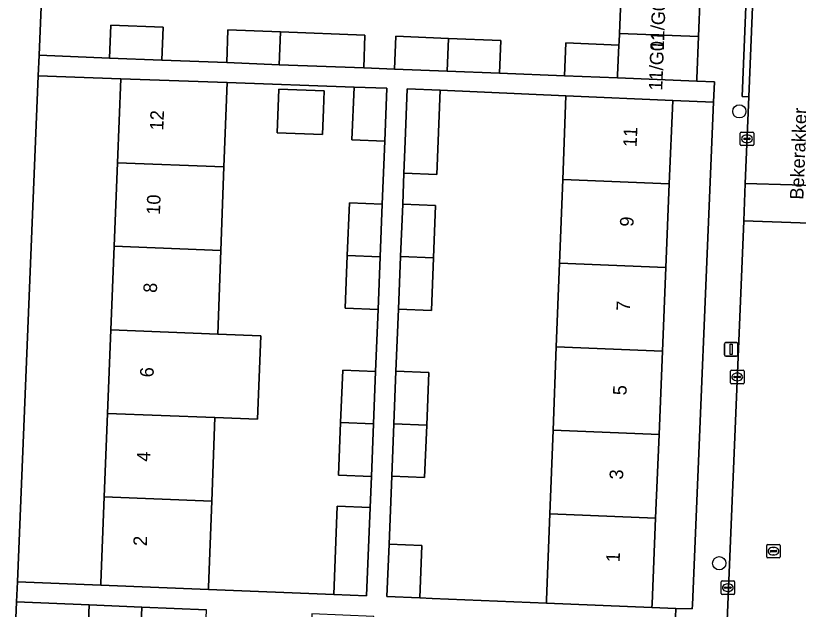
# Model space of a CAD drawing. Extents: x 161354 to 162026, y 386504 to 387460.
# Drawn here: x 161675.2 to 161732.9, y 386679.9 to 386723.6 of the extents above; entities that cross this region are included whole.
import ezdxf

# ---------------------------------------------------------------- set-up
doc = ezdxf.new("R2010")
doc.units = 0
for name, color, linetype in [('IMGEO_Boom', 7, 'Continuous'), ('IMGEO_Erf', 7, 'Continuous'), ('IMGEO_Kolk', 7, 'Continuous'), ('IMGEO_Lichtmast', 7, 'Continuous'), ('IMGEO_Openbare_ruimte_label', 7, 'Continuous'), ('IMGEO_Pand', 7, 'Continuous'), ('IMGEO_Pand_nummerreeks', 7, 'Continuous'), ('IMGEO_Rijbaan_lokaal_open', 7, 'Continuous'), ('IMGEO_Rioolput', 7, 'Continuous'), ('IMGEO_Voetpad_open', 7, 'Continuous')]:
    doc.layers.add(name, color=color, linetype=linetype)

msp = doc.modelspace()

# ---------------------------------------------------------------- linework, layer by layer
at = {"layer": 'IMGEO_Boom'}
for centre in [(161728.563, 386716.579), (161727.083, 386683.249)]:
    msp.add_circle(centre, 0.489, dxfattribs=at)
at = {"layer": 'IMGEO_Erf'}
for points in [[(161677.78, 386742.025), (161676.9, 386720.715), (161682.088, 386720.512), (161682.183, 386722.94), (161686.06, 386722.789), (161685.965, 386720.36), (161690.739, 386720.174), (161690.834, 386722.602), (161694.711, 386722.45), (161700.941, 386722.206), (161700.846, 386719.778), (161703.124, 386719.689), (161703.219, 386722.117), (161707.096, 386721.965), (161710.973, 386721.814), (161710.878, 386719.386), (161715.664, 386719.198), (161715.759, 386721.626), (161719.678, 386721.473), (161719.689, 386721.716), (161719.714, 386722.329), (161719.837, 386725.413)], [(161717.42, 386666.469), (161717.539, 386669.567), (161717.658, 386672.664), (161717.777, 386675.762), (161717.795, 386676.239), (161713.961, 386676.394), (161714.059, 386678.822), (161709.346, 386679.013), (161709.247, 386676.585), (161705.371, 386676.742), (161701.494, 386676.898), (161701.592, 386679.326), (161697.01, 386679.512), (161696.912, 386677.084), (161693.035, 386677.241), (161689.158, 386677.398), (161689.257, 386679.826), (161684.47, 386680.019), (161684.372, 386677.591), (161680.495, 386677.748), (161680.594, 386680.176), (161675.236, 386680.393), (161674.229, 386655.994)]]:
    msp.add_lwpolyline(points, dxfattribs=at)
for points in [[(161682.44, 386706.629), (161682.684, 386712.79), (161682.93, 386718.98), (161676.837, 386719.2), (161675.298, 386681.892), (161681.45, 386681.643), (161681.456, 386681.799), (161681.708, 386688.145), (161681.952, 386694.306), (161682.196, 386700.468)], [(161701.911, 386701.971), (161699.483, 386702.068), (161699.638, 386705.945), (161699.793, 386709.822), (161702.221, 386709.725), (161702.407, 386714.385), (161699.979, 386714.483), (161700.134, 386718.359), (161690.763, 386718.697), (161690.536, 386712.478), (161690.311, 386706.316), (161690.086, 386700.155), (161693.262, 386700.029), (161693.017, 386693.867), (161689.861, 386693.992), (161689.636, 386687.83), (161689.405, 386681.494), (161689.399, 386681.321), (161698.638, 386680.947), (161698.898, 386687.462), (161701.326, 386687.365), (161701.418, 386689.65), (161698.99, 386689.747), (161699.145, 386693.624), (161699.3, 386697.501), (161701.728, 386697.403)], [(161694.458, 386714.984), (161694.576, 386718.217), (161697.938, 386718.094), (161697.887, 386716.709), (161697.82, 386714.861)], [(161715.292, 386705.385), (161715.529, 386711.546), (161715.767, 386717.736), (161706.496, 386718.14), (161706.246, 386711.927), (161703.818, 386712.027), (161703.727, 386709.744), (161706.155, 386709.647), (161705.997, 386705.77), (161705.841, 386701.893), (161703.413, 386701.991), (161703.229, 386697.421), (161705.657, 386697.324), (161705.501, 386693.447), (161705.345, 386689.57), (161702.917, 386689.667), (161702.716, 386684.665), (161705.144, 386684.567), (161704.988, 386680.69), (161705.901, 386680.653), (161714.327, 386680.312), (161714.337, 386680.56), (161714.581, 386686.901), (161714.818, 386693.062), (161715.055, 386699.224)], [(161726.661, 386717.261), (161723.649, 386717.392), (161723.396, 386711.223), (161723.143, 386705.062), (161722.891, 386698.902), (161722.639, 386692.741), (161722.386, 386686.58), (161722.127, 386680.255), (161722.116, 386679.997), (161723.886, 386679.925), (161725.083, 386679.877), (161725.096, 386680.182)]]:
    msp.add_lwpolyline(points, close=True, dxfattribs=at)
at = {"layer": 'IMGEO_Kolk'}
for p, q in [((161728.625, 386714.128), (161728.625, 386714.98)), ((161728.7, 386715.054), (161729.552, 386715.054)), ((161729.113, 386714.834), (161729.138, 386714.834)), ((161729.626, 386714.98), (161729.626, 386714.128)), ((161728.884, 386714.548), (161728.884, 386714.56)), ((161729.322, 386714.511), (161728.924, 386714.511)), ((161728.927, 386714.597), (161729.325, 386714.597)), ((161729.136, 386714.274), (161729.111, 386714.274)), ((161729.368, 386714.56), (161729.368, 386714.548)), ((161729.552, 386714.054), (161728.7, 386714.054)), ((161727.983, 386697.49), (161728.835, 386697.49)), ((161727.908, 386696.564), (161727.908, 386697.416)), ((161728.167, 386696.984), (161728.167, 386696.996)), ((161728.605, 386696.947), (161728.207, 386696.947)), ((161728.21, 386697.033), (161728.608, 386697.033)), ((161728.396, 386697.27), (161728.421, 386697.27)), ((161728.651, 386696.996), (161728.651, 386696.984)), ((161728.909, 386697.416), (161728.909, 386696.564)), ((161728.835, 386696.49), (161727.983, 386696.49)), ((161728.419, 386696.71), (161728.394, 386696.71)), ((161727.215, 386681.024), (161727.215, 386681.876)), ((161727.29, 386681.95), (161728.142, 386681.95)), ((161728.216, 386681.876), (161728.216, 386681.024)), ((161727.474, 386681.444), (161727.474, 386681.456)), ((161727.912, 386681.407), (161727.514, 386681.407)), ((161727.517, 386681.493), (161727.915, 386681.493)), ((161727.703, 386681.73), (161727.728, 386681.73)), ((161727.958, 386681.456), (161727.958, 386681.444)), ((161728.142, 386680.95), (161727.29, 386680.95)), ((161727.726, 386681.17), (161727.701, 386681.17))]:
    msp.add_line(p, q, dxfattribs=at)
for points in [[(161728.625, 386714.128), (161728.625, 386714.98)], [(161728.7, 386715.054), (161729.552, 386715.054)], [(161729.626, 386714.98), (161729.626, 386714.128)], [(161729.552, 386714.054), (161728.7, 386714.054)], [(161727.983, 386697.49), (161728.835, 386697.49)], [(161727.908, 386696.564), (161727.908, 386697.416)], [(161728.909, 386697.416), (161728.909, 386696.564)], [(161728.835, 386696.49), (161727.983, 386696.49)], [(161727.215, 386681.024), (161727.215, 386681.876)], [(161727.29, 386681.95), (161728.142, 386681.95)], [(161728.216, 386681.876), (161728.216, 386681.024)], [(161728.142, 386680.95), (161727.29, 386680.95)]]:
    msp.add_lwpolyline(points, dxfattribs=at)
for centre, radius, start, end in [((161728.702, 386714.978), 0.0765, 91.55205, 178.44795), ((161728.702, 386714.978), 0.0765, 91.55205, 178.44795), ((161729.55, 386714.978), 0.0765, 1.55205, 88.44795), ((161729.55, 386714.978), 0.0765, 1.55205, 88.44795), ((161728.924, 386714.557), 0.0403, 85.87752, 175.75265), ((161728.921, 386714.547), 0.0366, 178.93798, 274.71019), ((161729.325, 386714.554), 0.043, 264.86636, 352.45326), ((161729.329, 386714.559), 0.0386, 1.73085, 96.63898), ((161728.702, 386714.13), 0.0765, 181.55205, 268.44795), ((161728.702, 386714.13), 0.0765, 181.55205, 268.44795), ((161729.55, 386714.13), 0.0765, 271.55205, 358.44795), ((161729.55, 386714.13), 0.0765, 271.55205, 358.44795), ((161727.985, 386697.414), 0.0765, 91.55205, 178.44795), ((161727.985, 386697.414), 0.0765, 91.55205, 178.44795), ((161728.833, 386697.414), 0.0765, 1.55205, 88.44795), ((161728.833, 386697.414), 0.0765, 1.55205, 88.44795), ((161728.207, 386696.993), 0.0403, 85.87752, 175.75265), ((161728.204, 386696.983), 0.0366, 178.93798, 274.71019), ((161728.608, 386696.99), 0.043, 264.86636, 352.45326), ((161728.612, 386696.995), 0.0386, 1.73085, 96.63898), ((161727.985, 386696.566), 0.0765, 181.55205, 268.44795), ((161727.985, 386696.566), 0.0765, 181.55205, 268.44795), ((161728.833, 386696.566), 0.0765, 271.55205, 358.44795), ((161728.833, 386696.566), 0.0765, 271.55205, 358.44795), ((161727.292, 386681.874), 0.0765, 91.55205, 178.44795), ((161727.292, 386681.874), 0.0765, 91.55205, 178.44795), ((161728.14, 386681.874), 0.0765, 1.55205, 88.44795), ((161728.14, 386681.874), 0.0765, 1.55205, 88.44795), ((161727.514, 386681.453), 0.0403, 85.87752, 175.75265), ((161727.511, 386681.443), 0.0366, 178.93798, 274.71019), ((161727.915, 386681.45), 0.043, 264.86636, 352.45326), ((161727.919, 386681.455), 0.0386, 1.73085, 96.63898), ((161727.292, 386681.026), 0.0765, 181.55205, 268.44795), ((161727.292, 386681.026), 0.0765, 181.55205, 268.44795), ((161728.14, 386681.026), 0.0765, 271.55205, 358.44795), ((161728.14, 386681.026), 0.0765, 271.55205, 358.44795)]:
    msp.add_arc(centre, radius, start, end, dxfattribs=at)
for centre, major_axis, ratio, start_param, end_param in [((161729.112, 386714.554), (-0.387, 0.002), 0.722429, 4.712389, 7.853982), ((161729.137, 386714.554), (-0.39, 0.002), 0.717154, 1.570796, 4.712389), ((161728.395, 386696.99), (-0.387, 0.002), 0.722429, 4.712389, 7.853982), ((161728.42, 386696.99), (-0.39, 0.002), 0.717154, 1.570796, 4.712389), ((161727.702, 386681.45), (-0.387, 0.002), 0.722429, 4.712389, 7.853982), ((161727.727, 386681.45), (-0.39, 0.002), 0.717154, 1.570796, 4.712389)]:
    msp.add_ellipse(centre, major_axis=major_axis, ratio=ratio, start_param=start_param, end_param=end_param, dxfattribs=at)
at = {"layer": 'IMGEO_Lichtmast'}
for p, q in [((161727.463, 386698.623), (161727.463, 386699.423)), ((161727.463, 386699.423), (161727.463, 386698.623)), ((161727.563, 386699.523), (161728.353, 386699.523)), ((161728.353, 386699.523), (161727.563, 386699.523)), ((161728.453, 386699.423), (161728.453, 386698.623)), ((161728.453, 386698.623), (161728.453, 386699.423)), ((161728.353, 386698.523), (161727.563, 386698.523)), ((161727.563, 386698.523), (161728.353, 386698.523))]:
    msp.add_line(p, q, dxfattribs=at)
msp.add_lwpolyline([(161727.883, 386699.398), (161728.033, 386699.398), (161728.033, 386698.648), (161727.883, 386698.648), (161727.883, 386699.398)], dxfattribs=at)
for centre, start, end in [((161727.563, 386699.423), 90, 180), ((161727.563, 386699.423), 90, 180), ((161728.353, 386699.423), 0, 90), ((161728.353, 386699.423), 360, 90), ((161727.563, 386698.623), 180, 270), ((161727.563, 386698.623), 180, 270), ((161728.353, 386698.623), 270, 0), ((161728.353, 386698.623), 270, 0)]:
    msp.add_arc(centre, 0.1, start, end, dxfattribs=at)
at = {"layer": 'IMGEO_Pand'}
for points in [[(161725.556, 386722.095), (161725.679, 386725.179), (161719.837, 386725.413), (161719.714, 386722.329)], [(161682.088, 386720.512), (161685.965, 386720.36), (161686.06, 386722.789), (161682.183, 386722.94)], [(161694.711, 386722.45), (161690.834, 386722.602), (161690.739, 386720.174), (161694.616, 386720.022)], [(161694.711, 386722.45), (161694.616, 386720.022), (161700.846, 386719.778), (161700.941, 386722.206)], [(161725.556, 386722.095), (161719.714, 386722.329), (161719.689, 386721.716), (161719.678, 386721.473), (161719.581, 386719.244), (161719.572, 386719.045), (161725.424, 386718.816), (161725.432, 386719.01)], [(161707.096, 386721.965), (161703.219, 386722.117), (161703.124, 386719.689), (161707.001, 386719.537)], [(161707.096, 386721.965), (161707.001, 386719.537), (161710.878, 386719.386), (161710.973, 386721.814)], [(161719.678, 386721.473), (161715.759, 386721.626), (161715.664, 386719.198), (161719.572, 386719.045), (161719.581, 386719.244)], [(161690.763, 386718.697), (161682.93, 386718.98), (161682.684, 386712.79), (161690.536, 386712.478)], [(161700.134, 386718.359), (161699.979, 386714.483), (161702.407, 386714.385), (161702.563, 386718.283)], [(161706.496, 386718.14), (161704.065, 386718.238), (161703.912, 386714.361), (161703.818, 386712.027), (161706.246, 386711.927)], [(161694.576, 386718.217), (161694.458, 386714.984), (161697.82, 386714.861), (161697.887, 386716.709), (161697.938, 386718.094)], [(161723.649, 386717.392), (161715.767, 386717.736), (161715.529, 386711.546), (161723.396, 386711.223)], [(161690.311, 386706.316), (161690.536, 386712.478), (161682.684, 386712.79), (161682.44, 386706.629)], [(161715.529, 386711.546), (161715.292, 386705.385), (161723.143, 386705.062), (161723.396, 386711.223)], [(161702.221, 386709.725), (161699.793, 386709.822), (161699.638, 386705.945), (161702.066, 386705.848)], [(161703.727, 386709.744), (161703.571, 386705.868), (161705.997, 386705.77), (161706.155, 386709.647)], [(161682.44, 386706.629), (161682.196, 386700.468), (161690.086, 386700.155), (161690.311, 386706.316)], [(161702.066, 386705.848), (161699.638, 386705.945), (161699.483, 386702.068), (161701.911, 386701.971)], [(161705.997, 386705.77), (161703.571, 386705.868), (161703.413, 386701.991), (161705.841, 386701.893)], [(161722.891, 386698.902), (161723.143, 386705.062), (161715.292, 386705.385), (161715.055, 386699.224)], [(161693.262, 386700.029), (161690.086, 386700.155), (161682.196, 386700.468), (161681.952, 386694.306), (161689.861, 386693.992), (161693.017, 386693.867)], [(161715.055, 386699.224), (161714.818, 386693.062), (161722.639, 386692.741), (161722.891, 386698.902)], [(161701.728, 386697.403), (161699.3, 386697.501), (161699.145, 386693.624), (161701.573, 386693.527)], [(161703.229, 386697.421), (161703.073, 386693.544), (161705.501, 386693.447), (161705.657, 386697.324)], [(161681.952, 386694.306), (161681.708, 386688.145), (161689.636, 386687.83), (161689.861, 386693.992)], [(161701.573, 386693.527), (161699.145, 386693.624), (161698.99, 386689.747), (161701.418, 386689.65)], [(161705.501, 386693.447), (161703.073, 386693.544), (161702.917, 386689.667), (161705.345, 386689.57)], [(161714.818, 386693.062), (161714.581, 386686.901), (161722.386, 386686.58), (161722.639, 386692.741)], [(161689.636, 386687.83), (161681.708, 386688.145), (161681.456, 386681.799), (161681.45, 386681.643), (161689.399, 386681.321), (161689.405, 386681.494)], [(161701.326, 386687.365), (161698.898, 386687.462), (161698.638, 386680.947), (161701.066, 386680.849)], [(161722.386, 386686.58), (161714.581, 386686.901), (161714.337, 386680.56), (161714.327, 386680.312), (161722.116, 386679.997), (161722.127, 386680.255)], [(161702.716, 386684.665), (161702.56, 386680.788), (161704.988, 386680.69), (161705.144, 386684.567)], [(161684.47, 386680.019), (161680.594, 386680.176), (161680.495, 386677.748), (161684.372, 386677.591)]]:
    msp.add_lwpolyline(points, close=True, dxfattribs=at)
at = {"layer": 'IMGEO_Rijbaan_lokaal_open'}
for points in [[(161737.515, 386750), (161737.664, 386757.8), (161738.131, 386768.811), (161731.175, 386769.153), (161730.711, 386758.025), (161730.697, 386753.106), (161730.304, 386743.254), (161730.096, 386738.148), (161729.261, 386717.657), (161729, 386711.269), (161735.937, 386711.052), (161736.362, 386721.528), (161736.628, 386728.094)], [(161735.824, 386708.256), (161735.937, 386711.052), (161729, 386711.269), (161728.888, 386708.517)]]:
    msp.add_lwpolyline(points, close=True, dxfattribs=at)
for points in [[(161674.229, 386655.994), (161675.236, 386680.393), (161675.298, 386681.892), (161676.837, 386719.2), (161676.9, 386720.715), (161677.78, 386742.025)], [(161735.471, 386699.54), (161735.824, 386708.256), (161728.888, 386708.517), (161728.502, 386699.051), (161727.654, 386679.034), (161726.868, 386660.492), (161726.622, 386654.699)]]:
    msp.add_lwpolyline(points, dxfattribs=at)
at = {"layer": 'IMGEO_Rioolput'}
for p, q in [((161730.579, 386683.716), (161730.579, 386684.568)), ((161730.654, 386684.642), (161731.506, 386684.642)), ((161730.881, 386684.185), (161731.279, 386684.185)), ((161731.067, 386684.422), (161731.092, 386684.422)), ((161731.58, 386684.568), (161731.58, 386683.716)), ((161731.506, 386683.642), (161730.654, 386683.642)), ((161730.838, 386684.136), (161730.838, 386684.148)), ((161731.276, 386684.099), (161730.878, 386684.099)), ((161731.09, 386683.862), (161731.065, 386683.862)), ((161731.322, 386684.148), (161731.322, 386684.136))]:
    msp.add_line(p, q, dxfattribs=at)
for points in [[(161730.579, 386683.716), (161730.579, 386684.568)], [(161730.654, 386684.642), (161731.506, 386684.642)], [(161731.58, 386684.568), (161731.58, 386683.716)], [(161731.506, 386683.642), (161730.654, 386683.642)]]:
    msp.add_lwpolyline(points, dxfattribs=at)
for centre, radius, start, end in [((161730.656, 386684.566), 0.0765, 91.55205, 178.44795), ((161730.656, 386684.566), 0.0765, 91.55205, 178.44795), ((161730.878, 386684.145), 0.0403, 85.87752, 175.75265), ((161731.283, 386684.147), 0.0386, 1.73085, 96.63898), ((161731.504, 386684.566), 0.0765, 1.55205, 88.44795), ((161731.504, 386684.566), 0.0765, 1.55205, 88.44795), ((161730.656, 386683.718), 0.0765, 181.55205, 268.44795), ((161730.656, 386683.718), 0.0765, 181.55205, 268.44795), ((161730.875, 386684.135), 0.0366, 178.93798, 274.71019), ((161731.279, 386684.142), 0.043, 264.86636, 352.45326), ((161731.504, 386683.718), 0.0765, 271.55205, 358.44795), ((161731.504, 386683.718), 0.0765, 271.55205, 358.44795)]:
    msp.add_arc(centre, radius, start, end, dxfattribs=at)
for centre, major_axis, ratio, start_param, end_param in [((161731.066, 386684.142), (-0.387, 0.002), 0.722429, 4.712389, 7.853982), ((161731.091, 386684.142), (-0.39, 0.002), 0.717154, 1.570796, 4.712389)]:
    msp.add_ellipse(centre, major_axis=major_axis, ratio=ratio, start_param=start_param, end_param=end_param, dxfattribs=at)
at = {"layer": 'IMGEO_Voetpad_open'}
for points in [[(161728.502, 386699.051), (161728.888, 386708.517), (161729, 386711.269), (161729.261, 386717.657), (161728.763, 386717.677), (161729.6, 386738.168)], [(161725.679, 386725.179), (161725.556, 386722.095), (161725.432, 386719.01), (161725.424, 386718.816), (161726.724, 386718.765), (161726.661, 386717.261), (161725.096, 386680.182), (161725.083, 386679.877), (161723.886, 386679.925), (161723.833, 386678.632), (161723.825, 386678.427), (161723.714, 386675.534), (161723.595, 386672.437), (161723.476, 386669.339), (161723.358, 386666.241), (161723.239, 386663.144), (161723.12, 386660.046), (161724.259, 386660.073), (161724.096, 386654.913)], [(161723.833, 386678.632), (161723.886, 386679.925), (161722.116, 386679.997), (161714.327, 386680.312), (161705.901, 386680.653), (161704.988, 386680.69), (161702.56, 386680.788), (161702.716, 386684.665), (161702.917, 386689.667), (161703.073, 386693.544), (161703.229, 386697.421), (161703.413, 386701.991), (161703.571, 386705.868), (161703.727, 386709.744), (161703.818, 386712.027), (161703.912, 386714.361), (161704.065, 386718.238), (161706.496, 386718.14), (161715.767, 386717.736), (161723.649, 386717.392), (161726.661, 386717.261), (161726.724, 386718.765), (161725.424, 386718.816), (161719.572, 386719.045), (161715.664, 386719.198), (161710.878, 386719.386), (161707.001, 386719.537), (161703.124, 386719.689), (161700.846, 386719.778), (161694.616, 386720.022), (161690.739, 386720.174), (161685.965, 386720.36), (161682.088, 386720.512), (161676.9, 386720.715), (161676.837, 386719.2), (161682.93, 386718.98), (161690.763, 386718.697), (161700.134, 386718.359), (161702.563, 386718.283), (161702.407, 386714.385), (161702.221, 386709.725), (161702.066, 386705.848), (161701.911, 386701.971), (161701.728, 386697.403), (161701.573, 386693.527), (161701.418, 386689.65), (161701.326, 386687.365), (161701.066, 386680.849), (161698.638, 386680.947), (161689.399, 386681.321), (161681.45, 386681.643), (161675.298, 386681.892), (161675.236, 386680.393), (161680.594, 386680.176), (161684.47, 386680.019), (161689.257, 386679.826)], [(161726.622, 386654.699), (161726.868, 386660.492), (161726.36, 386660.511), (161727.119, 386679.055), (161727.654, 386679.034), (161728.502, 386699.051)]]:
    msp.add_lwpolyline(points, dxfattribs=at)
msp.add_lwpolyline([(161729.261, 386717.657), (161730.096, 386738.148), (161729.6, 386738.168), (161728.763, 386717.677)], close=True, dxfattribs=at)

# ---------------------------------------------------------------- texts
at = {"layer": 'IMGEO_Openbare_ruimte_label'}
msp.add_text('Bekerakker', height=1, rotation=87.7071, dxfattribs=at).set_placement((161733.284, 386710.056))
at = {"layer": 'IMGEO_Pand_nummerreeks'}
for s, rotation, p in [('11/G02', 87.80124, (161722.988, 386721.06)), ('11/G01', 87.80005, (161722.874, 386718.105)), ('12', 87.7313, (161686.061, 386715.157)), ('11', 87.65108, (161720.984, 386713.926)), ('10', 87.73004, (161685.815, 386708.94)), ('9', 87.65393, (161720.743, 386708.056)), ('8', 87.73004, (161685.586, 386703.178)), ('7', 87.65393, (161720.489, 386701.84)), ('6', 87.7313, (161685.339, 386696.95)), ('5', 87.65393, (161720.234, 386695.624)), ('4', 87.73004, (161685.093, 386690.728)), ('3', 87.65393, (161719.979, 386689.408)), ('2', 87.7313, (161684.846, 386684.503)), ('1', 87.65108, (161719.73, 386683.305))]:
    msp.add_text(s, height=1, rotation=rotation, dxfattribs=at).set_placement(p)

doc.saveas('drawing.dxf')
